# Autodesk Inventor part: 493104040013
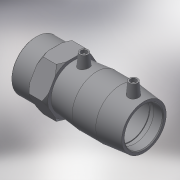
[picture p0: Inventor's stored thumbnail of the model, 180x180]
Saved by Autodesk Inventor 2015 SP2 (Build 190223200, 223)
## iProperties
Created: 2017-06
Part Number: 493104040013
Material: Generic
Description: PLASSON FEMALE TRANSITION COUPLER 40-1.1/4"
Document SubType Name: Modeling
Designer: KIM
Mass: 172.742 g
Surface Area: 416.134 cm^2
Volume: 172.742 cm^3
Density: 1 g/cm^3
Appearance: Default
Author: KIM
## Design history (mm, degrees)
derived "493104.ipt"
feature "Solid1::493104.ipt"
tag "TaggingFeature1"
body "Solid1"
other parameters: "d0" = 97, "d2" = 56, "d3" = 47, "d4" = 32.33333, "d5" = 50.4, "d6" = 38, "d8" = 168 deg, "d10" = 18.8, "d11" = 6.26667, "d29" = 46, "d30" = 14, "d31" = 33.95, "d34" = 5 deg, "d41" = 4, "d42" = 14, "d43" = 0, "d48" = 3, "d49" = 0, "d55" = 25, "d57" = 29, "d59" = 38.952, "d60" = 22.5, "d70" = 56, "d71" = 12.5, "d72" = 0, "d73" = 45 deg, "d74" = 2.9, "d75" = 45 deg, "d77" = 0.6, "d80" = 0.8, "L_" = 122, "L_1" = 47, "D_1" = 56, "A_" = 46, "d_2" = 12, "L_2" = 25, "D_" = 29, "R_p" = 38.952
